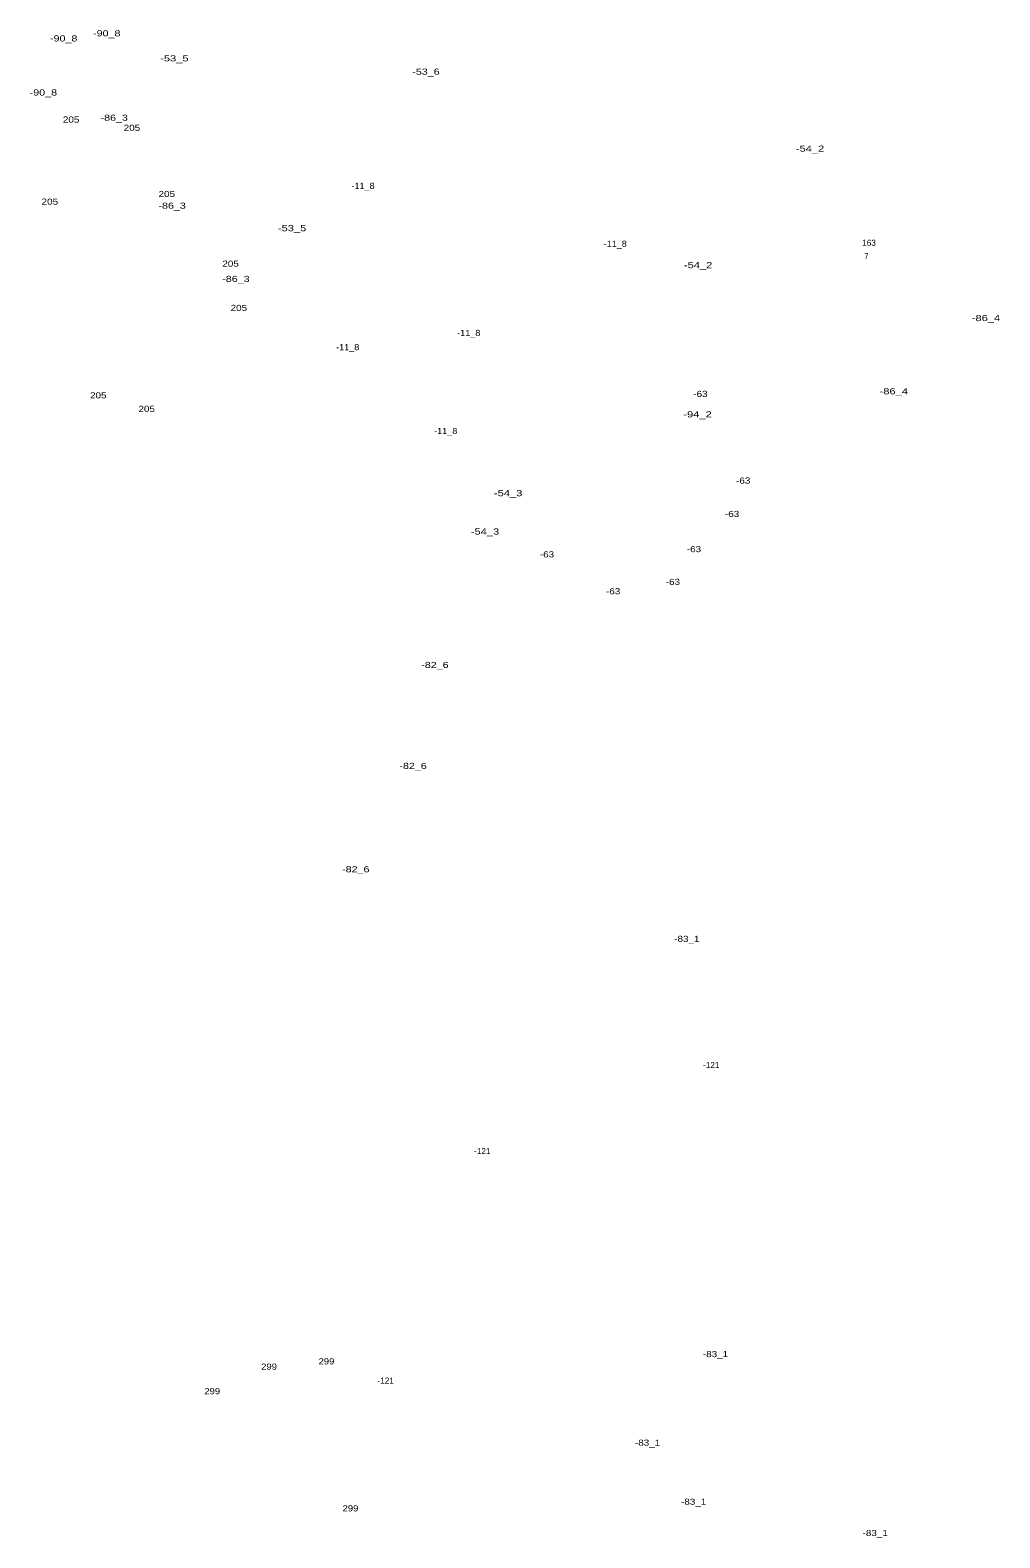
# Model space of a CAD drawing. Extents: x -662996 to -659766, y -998554 to -993949.
# Drawn here: x -662916 to -662286, y -997268 to -996287 of the extents above; entities that cross this region are included whole.
import ezdxf
from ezdxf.enums import TextEntityAlignment as Align

# ---------------------------------------------------------------- set-up
doc = ezdxf.new("R2010")
doc.units = 0
doc.header["$LTSCALE"] = 1.6
doc.layers.add('24', color=7, linetype='Continuous')

msp = doc.modelspace()

# ---------------------------------------------------------------- texts
at = {"layer": '24'}
for s, width, p in [('-90_8', 1.3, (-662894.47, -996294.13)), ('-90_8', 1.3, (-662866.49, -996290.82)), ('-53_5', 1.35, (-662822.51, -996307.09)), ('-53_6', 1.3, (-662658.95, -996315.76)), ('-90_8', 1.3, (-662907.69, -996329.31)), ('205', 1.2, (-662889.66, -996346.92)), ('-86_3', 1.3, (-662861.62, -996345.72)), ('205', 1.2, (-662850.11, -996352.29)), ('-54_2', 1.35, (-662409.23, -996365.81)), ('-11_8', 1.1, (-662699.84, -996390.08)), ('205', 1.2, (-662903.49, -996400.31)), ('-86_3', 1.3, (-662823.98, -996402.95)), ('205', 1.2, (-662827.449, -996395.32)), ('-53_5', 1.35, (-662745.97, -996417.57)), ('-11_8', 1.1, (-662535.87, -996427.73)), ('205', 1.2, (-662785.98, -996440.65)), ('-54_2', 1.35, (-662481.97, -996441.62)), ('7', 0.9, (-662372.54, -996435.72)), ('-86_3', 1.3, (-662782.51, -996450.59)), ('205', 1.2, (-662780.6, -996469.46)), ('-86_4', 1.35, (-662294.85, -996476.04)), ('-11_8', 1.1, (-662631.1, -996485.74)), ('-11_8', 1.1, (-662709.819, -996494.96)), ('205', 1.2, (-662872, -996526.32)), ('-63', 1.2, (-662480.48, -996525.39)), ('-86_4', 1.35, (-662354.76, -996523.67)), ('205', 1.2, (-662840.51, -996535.15)), ('-94_2', 1.35, (-662482.37, -996538.69)), ('-11_8', 1.1, (-662646.079, -996549.51)), ('-54_3', 1.35, (-662605.52, -996589.95)), ('-63', 1.2, (-662452.69, -996581.77)), ('-63', 1.2, (-662459.92, -996603.49)), ('-54_3', 1.35, (-662620.56, -996614.9)), ('-63', 1.2, (-662484.67, -996626.35)), ('-63', 1.2, (-662580.26, -996629.77)), ('-63', 1.2, (-662498.38, -996647.68)), ('-63', 1.2, (-662537.23, -996653.77)), ('-82_6', 1.3, (-662653.11, -996701.72)), ('-82_6', 1.3, (-662667.32, -996767.41)), ('-82_6', 1.3, (-662704.57, -996834.63)), ('-83_1', 1.2, (-662489.299, -996879.93)), ('299', 1.15, (-662760.96, -997158.19)), ('299', 1.15, (-662723.64, -997154.76)), ('-83_1', 1.2, (-662470.669, -997150.01)), ('299', 1.15, (-662797.9, -997174.19)), ('-83_1', 1.2, (-662514.829, -997207.65)), ('-83_1', 1.2, (-662484.88, -997246.06)), ('299', 1.15, (-662708.03, -997250.38)), ('-83_1', 1.2, (-662366.84, -997266.41))]:
    msp.add_text(s, height=4, dxfattribs=dict(at, width=width)).set_placement(p, align=Align.CENTER)
for s, p in [('163', (-662370.88, -996427.05)), ('-121', (-662473.41, -996961.96)), ('-121', (-662622.301, -997017.96)), ('-121', (-662685.14, -997167.3))]:
    msp.add_text(s, height=4, dxfattribs=at).set_placement(p, align=Align.CENTER)

doc.saveas('drawing.dxf')
